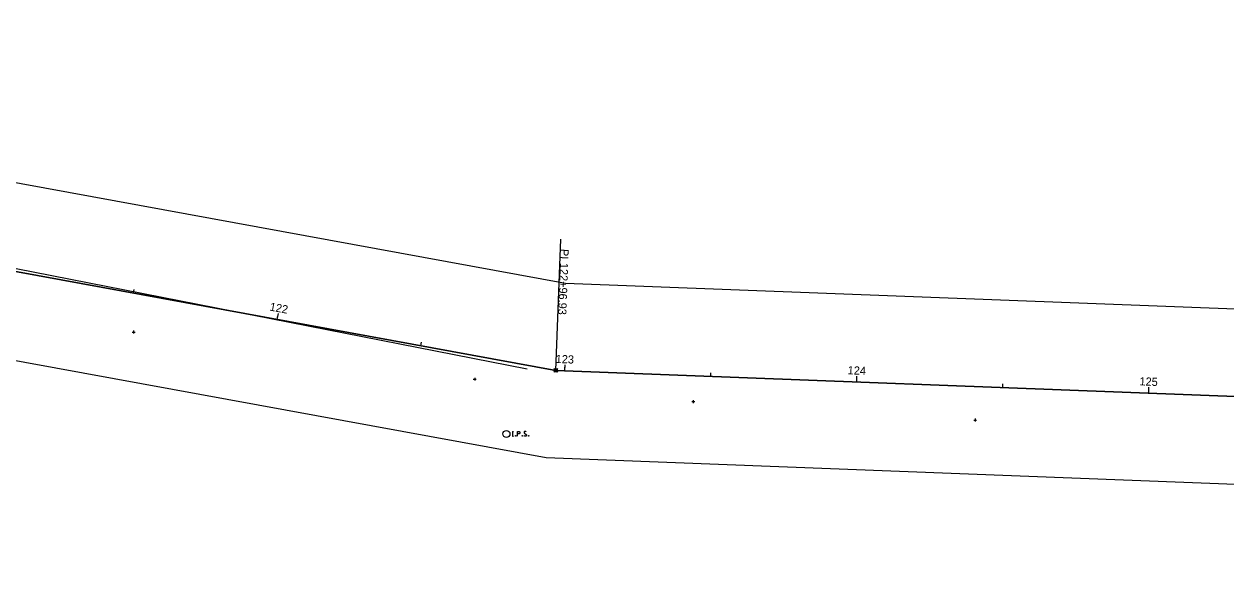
# Model space of a CAD drawing. Extents: x 2003596 to 2006888, y 571866 to 574416.
# Drawn here: x 2004849.5 to 2005260.9, y 572567.3 to 572754 of the extents above; entities that cross this region are included whole.
import ezdxf

# ---------------------------------------------------------------- set-up
doc = ezdxf.new("R2010")
doc.units = 0
for name, color, linetype in [('GE_X_Alignment', 7, 'Continuous'), ('GE_X_Alignment_1000_Cardinal_Points', 7, 'Continuous'), ('GE_X_Alignment_1000_Stations', 7, 'Continuous'), ('GE_X_Alignment_100_Cardinal_Points', 7, 'Continuous'), ('GE_X_Alignment_100_Stations', 7, 'Continuous'), ('GE_X_Alignment_500_Cardinal_Points', 7, 'Continuous'), ('GE_X_Alignment_500_Stations', 7, 'Continuous'), ('RW_X_CL', 7, 'Continuous'), ('RW_X_Esmt_SH', 7, 'Continuous'), ('SC_Scratch1', 7, 'Continuous'), ('SC_Scratch8', 7, 'Continuous'), ('SV_P_Mon_Cells_Set', 7, 'Continuous'), ('SV_X_Random_Point', 7, 'Continuous'), ('SV_X_Shot_Marker', 7, 'Continuous')]:
    doc.layers.add(name, color=color, linetype=linetype)

msp = doc.modelspace()

# ---------------------------------------------------------------- linework, layer by layer
at = {"layer": 'GE_X_Alignment'}
for p, q in [((2004545, 572724.5), (2005031.48, 572635.32)), ((2005031.48, 572635.32), (2006023.62, 572597.25))]:
    msp.add_line(p, q, dxfattribs=at)
at = {"layer": 'GE_X_Alignment_1000_Cardinal_Points'}
msp.add_line((2005031.48, 572635.32), (2005033.2, 572680.29), dxfattribs=at)
msp.add_circle((2005031.48, 572635.32), 0.6, dxfattribs=at)
at = {"layer": 'GE_X_Alignment_1000_Stations'}
msp.add_line((2005234.4, 572627.53), (2005234.45, 572628.73), dxfattribs=at)
at = {"layer": 'GE_X_Alignment_100_Cardinal_Points'}
msp.add_line((2005031.48, 572635.32), (2005033.2, 572680.29), dxfattribs=at)
msp.add_circle((2005031.48, 572635.32), 0.6, dxfattribs=at)
at = {"layer": 'GE_X_Alignment_100_Stations'}
for p, q in [((2004886.96, 572661.81), (2004887.18, 572662.99)), ((2004936.14, 572652.8), (2004936.5, 572654.76)), ((2004985.32, 572643.78), (2004985.54, 572644.96)), ((2005034.55, 572635.2), (2005034.63, 572637.2)), ((2005084.51, 572633.28), (2005084.56, 572634.48)), ((2005134.47, 572631.37), (2005134.55, 572633.37)), ((2005184.44, 572629.45), (2005184.48, 572630.65)), ((2005234.4, 572627.53), (2005234.48, 572629.53))]:
    msp.add_line(p, q, dxfattribs=at)
at = {"layer": 'GE_X_Alignment_500_Cardinal_Points'}
msp.add_line((2005031.48, 572635.32), (2005033.2, 572680.29), dxfattribs=at)
msp.add_circle((2005031.48, 572635.32), 0.6, dxfattribs=at)
at = {"layer": 'GE_X_Alignment_500_Stations'}
for p, q in [((2004936.14, 572652.8), (2004936.36, 572653.98)), ((2005034.55, 572635.2), (2005034.59, 572636.4)), ((2005134.47, 572631.37), (2005134.52, 572632.57)), ((2005234.4, 572627.53), (2005234.48, 572629.53))]:
    msp.add_line(p, q, dxfattribs=at)
at = {"layer": 'RW_X_CL'}
for p, q in [((2005031.48, 572635.32), (2004545, 572724.5)), ((2006023.62, 572597.25), (2005031.48, 572635.32))]:
    msp.add_line(p, q, dxfattribs=at)
at = {"layer": 'RW_X_Esmt_SH'}
for p, q in [((2004550.41, 572754.01), (2005034.78, 572665.22)), ((2004539.59, 572694.99), (2005028.18, 572605.42)), ((2005034.78, 572665.22), (2006024.45, 572627.24)), ((2005028.18, 572605.42), (2006022.8, 572567.26))]:
    msp.add_line(p, q, dxfattribs=at)
at = {"layer": 'SC_Scratch1'}
msp.add_line((2004433.11, 572745.04), (2005031.48, 572635.32), dxfattribs=at)
at = {"layer": 'SC_Scratch8'}
msp.add_line((2005021.66, 572635.7), (2004450.87, 572747.83), dxfattribs=at)
at = {"layer": 'SV_P_Mon_Cells_Set'}
for points in [[(2005016.59, 572614.35), (2005016.95, 572614.35)], [(2005016.59, 572612.75), (2005016.95, 572612.75)], [(2005016.77, 572612.75), (2005016.77, 572614.35)], [(2005017.73, 572612.97), (2005017.79, 572612.97), (2005017.82, 572612.94), (2005017.85, 572612.89), (2005017.85, 572612.83), (2005017.82, 572612.78), (2005017.79, 572612.75), (2005017.73, 572612.75), (2005017.7, 572612.78), (2005017.66, 572612.83), (2005017.66, 572612.89), (2005017.7, 572612.94), (2005017.73, 572612.97)], [(2005018.34, 572612.75), (2005018.34, 572614.35), (2005018.87, 572614.35), (2005018.92, 572614.34), (2005019, 572614.32), (2005019.03, 572614.29), (2005019.06, 572614.27), (2005019.11, 572614.2), (2005019.14, 572614.14), (2005019.16, 572614.04), (2005019.16, 572613.89), (2005019.15, 572613.84), (2005019.13, 572613.76), (2005019.09, 572613.67), (2005019.04, 572613.64), (2005019.01, 572613.61), (2005018.95, 572613.59), (2005018.87, 572613.57), (2005018.34, 572613.57)], [(2005019.98, 572612.97), (2005020.03, 572612.97), (2005020.07, 572612.94), (2005020.1, 572612.89), (2005020.1, 572612.83), (2005020.07, 572612.78), (2005020.03, 572612.75), (2005019.98, 572612.75), (2005019.95, 572612.78), (2005019.91, 572612.83), (2005019.91, 572612.89), (2005019.95, 572612.94), (2005019.98, 572612.97)], [(2005021.35, 572614.24), (2005021.32, 572614.27), (2005021.29, 572614.29), (2005021.19, 572614.33), (2005021.07, 572614.35), (2005020.98, 572614.35), (2005020.95, 572614.35), (2005020.81, 572614.32), (2005020.68, 572614.24), (2005020.61, 572614.14), (2005020.59, 572614.04), (2005020.59, 572613.96), (2005020.61, 572613.86), (2005020.7, 572613.78), (2005021.3, 572613.4), (2005021.36, 572613.35), (2005021.38, 572613.3), (2005021.4, 572613.22), (2005021.4, 572613.15), (2005021.39, 572613.07), (2005021.38, 572613.02), (2005021.36, 572612.96), (2005021.33, 572612.91), (2005021.31, 572612.87), (2005021.28, 572612.83), (2005021.25, 572612.81), (2005021.2, 572612.78), (2005021.17, 572612.77), (2005021.07, 572612.75), (2005020.92, 572612.75), (2005020.82, 572612.78), (2005020.67, 572612.87), (2005020.59, 572612.94)], [(2005022.16, 572612.97), (2005022.22, 572612.97), (2005022.25, 572612.94), (2005022.28, 572612.89), (2005022.28, 572612.83), (2005022.25, 572612.78), (2005022.22, 572612.75), (2005022.16, 572612.75), (2005022.13, 572612.78), (2005022.1, 572612.83), (2005022.1, 572612.89), (2005022.13, 572612.94), (2005022.16, 572612.97)]]:
    msp.add_lwpolyline(points, dxfattribs=at)
msp.add_circle((2005014.58, 572613.55), 1.2, dxfattribs=at)
at = {"layer": 'SV_X_Random_Point'}
for p, q in [((2005030.81, 572634.65), (2005032.15, 572635.99)), ((2005030.81, 572635.99), (2005032.15, 572634.65))]:
    msp.add_line(p, q, dxfattribs=at)
at = {"layer": 'SV_X_Shot_Marker'}
for p, q in [((2004886.45, 572648.44), (2004887.45, 572648.44)), ((2004886.95, 572648.94), (2004886.95, 572647.94)), ((2004886.95, 572648.44), (2004886.95, 572648.44)), ((2005003.23, 572632.3), (2005004.23, 572632.3)), ((2005003.73, 572632.8), (2005003.73, 572631.8)), ((2005003.73, 572632.3), (2005003.73, 572632.3)), ((2005078.02, 572624.61), (2005079.02, 572624.61)), ((2005078.52, 572625.11), (2005078.52, 572624.11)), ((2005078.52, 572624.61), (2005078.52, 572624.61)), ((2005174.5, 572618.29), (2005175.5, 572618.29)), ((2005175, 572618.79), (2005175, 572617.79)), ((2005175, 572618.29), (2005175, 572618.29))]:
    msp.add_line(p, q, dxfattribs=at)

# ---------------------------------------------------------------- texts
at = {"layer": 'GE_X_Alignment_1000_Cardinal_Points'}
for s, p in [('PI', (2005033.12, 572676.98)), ('122+96.93', (2005032.94, 572672.2))]:
    msp.add_text(s, height=2.8, rotation=267.8026, dxfattribs=at).set_placement(p)
at = {"layer": 'GE_X_Alignment_100_Cardinal_Points'}
for s, p in [('PI', (2005033.12, 572676.98)), ('122+96.93', (2005032.94, 572672.2))]:
    msp.add_text(s, height=2.8, rotation=267.8026, dxfattribs=at).set_placement(p)
at = {"layer": 'GE_X_Alignment_100_Stations'}
for s, rotation, p in [('122', 349.6122, (2004933.37, 572655.85)), ('123', 357.8026, (2005031.38, 572637.87)), ('124', 357.8026, (2005131.33, 572633.99)), ('125', 357.8026, (2005231.21, 572630.2))]:
    msp.add_text(s, height=2.8, rotation=rotation, dxfattribs=at).set_placement(p)
at = {"layer": 'GE_X_Alignment_500_Cardinal_Points'}
for s, p in [('PI', (2005033.12, 572676.98)), ('122+96.93', (2005032.94, 572672.2))]:
    msp.add_text(s, height=2.8, rotation=267.8026, dxfattribs=at).set_placement(p)
at = {"layer": 'GE_X_Alignment_500_Stations'}
msp.add_text('125', height=2.8, rotation=357.8026, dxfattribs=at).set_placement((2005231.21, 572630.2))

doc.saveas('drawing.dxf')
